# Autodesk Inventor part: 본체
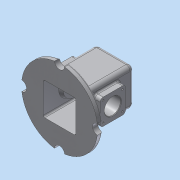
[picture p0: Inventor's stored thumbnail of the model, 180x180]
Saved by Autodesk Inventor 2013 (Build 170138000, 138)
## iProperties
Created: 2018-07
Part Number: 본체
Material: 알루미늄 6061
Document SubType Name: Modeling
Designer: Administrator
Density: 2.71 g/cm^3
Mass: 912.845 g
Surface Area: 1019.25 cm^2
Volume: 336.843 cm^3
Author: Administrator
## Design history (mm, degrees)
sketch "스케치1"
  geometry: L1 (0, 0)-(-99.447, 0); L2 (0, 0)-(0, -89.26); C1 r 75 at (0, 0); 1 further point
  constraints: 4 end point, 1 centre point, 1 coincident, 1 horizontal, 1 perpendicular
  dimensions: "d0" = 150 diameter of C1
extrude "돌출1" new body sketch "스케치1" distance "d2" = 10; taper "d3" = 0 deg
sketch "스케치2"
  geometry: L1 (0, 0)-(98.616, 0); L2 (0, 0)-(0, 93.63); C1 r 10 at (0, 75); C2 r 10 at (-75, 0); C3 r 10 at (0, -75); C4 r 10 at (75, 0)
  constraints: 4 centre point, 4 end point, 1 horizontal, 1 perpendicular, 1 point on line, 1 vertical alignment, 10 other
  dimensions: "d4" = 20 diameter of C1; "d8" = 360 deg dimension on L1.start C1.centre (derived)
extrude "돌출2" cut sketch "스케치2" distance "d10" = 10; taper "d11" = 0 deg
sketch "스케치3"
  geometry: L1 (-37, -37)-(37, -37); L2 (37, -37)-(37, 37); L3 (37, 37)-(-37, 37); L4 (-37, 37)-(-37, -37); L5 (-37, -37)-(37, 37); L6 (37, -37)-(-37, 37); A1 r 75 centre (0, 0) between (9.978, -74.333) and (74.333, -9.978) reference
  constraints: 12 end point, 2 midpoint, 2 parallel, 1 horizontal, 1 perpendicular
  dimensions: "d12" = 74 distance between parallel lines of L2 L4; "d14" = 74 distance between parallel lines of L3 L1
extrude "돌출3" join sketch "스케치3" distance "d15" = 100; taper "d16" = 0 deg
sketch "스케치4"
  geometry: L1 (-20, -20)-(20, -20); L2 (20, -20)-(20, 20); L3 (20, 20)-(-20, 20); L4 (-20, 20)-(-20, -20); L5 (-20, -20)-(20, 20); L6 (20, -20)-(-20, 20); 1 further point
  constraints: 12 end point, 2 midpoint, 2 parallel, 1 horizontal, 1 perpendicular
  dimensions: "d17" = 40 distance between parallel lines of L3 L1; "d19" = 40 distance between parallel lines of L4 L2
extrude "돌출4" join sketch "스케치4" distance "d20" = 7; taper "d21" = 0 deg
sketch "스케치5"
  geometry: C1 r 17.5 at (0, 0); 1 further point
  constraints: 1 centre point, 1 coincident
  dimensions: "d24" = 35 diameter of C1
extrude "돌출5" join sketch "스케치5" distance "d22" = 3; taper "d23" = 0 deg
sketch "스케치6"
  geometry: L1 (-32, 0)-(-32, 105); L2 (-32, 105)-(32, 105); L3 (32, 105)-(32, 0); L4 (32, 0)-(-32, 0); L5 (37, 110)-(-37, 110) reference; L6 (-37, 10)-(-37, 110) reference; L7 (37, 10)-(37, 110) reference; 1 further point
  constraints: 8 end point, 2 parallel, 1 midpoint, 1 perpendicular, 1 vertical
  dimensions: "d26" = 5 distance between parallel lines of L5 L2; "d27" = 5 distance between parallel lines of L7 L3; "d28" = 5 distance between parallel lines of L6 L1
extrude "돌출6" cut sketch "스케치6" stored distance "d29" = 64; taper "d30" = 0 deg
sketch "스케치8"
  geometry: L1 (12, 20)-(62, 20); L2 (62, 20)-(62, 70); L3 (62, 70)-(12, 70); L4 (12, 70)-(12, 20); L5 (12, 20)-(62, 70); L6 (62, 20)-(12, 70); L7 (37, -10)-(37, 143.948); L8 (46.978, -10)-(111.333, -10) reference; 2 further points
  constraints: 14 end point, 3 midpoint, 3 parallel, 1 horizontal, 1 perpendicular, 1 point on line
  dimensions: "d31" = 50 distance between parallel lines of L3 L1; "d33" = 50 distance between parallel lines of L4 L2; "d34" = 55 distance from line of point (37, 45) L8
extrude "돌출7" join sketch "스케치8" distance "d35" = 13; taper "d36" = 0 deg
sketch "스케치9"
  geometry: L1 (12, 20)-(62, 20); L2 (62, 20)-(62, 70); L3 (62, 70)-(12, 70); L4 (12, 70)-(12, 20); L5 (12, 20)-(62, 70); L6 (62, 20)-(12, 70); L7 (37, -10)-(37, 135.197); L8 (46.978, -10)-(111.333, -10) reference; 2 further points
  constraints: 14 end point, 3 midpoint, 3 parallel, 1 horizontal, 1 perpendicular, 1 point on line
  dimensions: "d37" = 50 distance between parallel lines of L3 L1; "d39" = 50 distance between parallel lines of L4 L2; "d40" = 55 distance from line of point (37, 45) L8
extrude "돌출8" join sketch "스케치9" distance "d41" = 13; taper "d42" = 0 deg
sketch "스케치10"
  geometry: L1 (-89.326, 55)-(79.755, 55); L2 (32, 0)-(-32, 0) reference; L3 (-32, 80)-(-25, 77.452); L4 (-25, 77.452)-(-25, 32.548); L5 (-25, 32.548)-(-32, 30); L6 (-32, 30)-(-32, 80); L7 (-32, 0)-(-32, 105) reference; L8 (32, 105)-(32, 0) reference; L9 (-32, 55)-(-32, 80); L10 (-25, 55)-(-25, 77.452); L11 (-25, 55)-(-32, 55); L12 (0, 0)-(0, 157.178); L13 (25, 55)-(25, 77.452); L14 (32, 55)-(32, 80); L15 (32, 80)-(25, 77.452); L16 (25, 55)-(32, 55)
  constraints: 26 end point, 4 symmetric about line, 2 collinear, 2 midpoint, 2 perpendicular, 1 horizontal, 1 point on line, 1 vertical
  dimensions: "d43" = 55 distance between parallel lines of L1 L2; "d45" = 7 distance between parallel lines of L7 L4; "d46" = 110 deg angle of L5 L7; "d47" = 110 deg angle of L7 L3; "d48" = 7 distance between parallel lines of L4 L6; "d49" = 25 distance from line of L3.start L1
revolve "회전1" sketch "스케치10" stored, may be unused: angle "d50" = 90 deg
sketch "스케치11"
  geometry: L1 (12, 70)-(12, 20) reference; L2 (12, 20)-(62, 70); L3 (62, 20)-(12, 70); C1 r 16 at (37, 45); 1 further point
  constraints: 4 end point, 1 centre point, 1 perpendicular, 1 point on line
  dimensions: "d51" = 32 diameter of C1
extrude "돌출9" cut sketch "스케치11" distance "d53" = 110; taper "d54" = 0 deg
sketch "스케치12"
  geometry: C1 r 17.5 at (0, 0) reference; C2 r 14 at (0, 0)
  constraints: 1 centre point, 1 coincident
  dimensions: "d55" = 28 diameter of C2
extrude "돌출10" cut sketch "스케치12" distance "d57" = 4; taper "d58" = 0 deg
sketch "스케치13"
  geometry: C1 r 14 at (0, 0) reference; C2 r 10.5 at (0, 0)
  constraints: 1 centre point, 1 coincident
  dimensions: "d59" = 21 diameter of C2
extrude "돌출11" cut sketch "스케치13" distance "d61" = 110; taper "d62" = 0 deg
fillet "모깎기1" dims "d63" = 6
fillet "모깎기2" dims "d64" = 6
sketch "스케치15"
  geometry: A1 r 6 centre (56, 26) between (56, 20) and (62, 26) reference; A2 r 6 centre (56, 64) between (62, 64) and (56, 70) reference; A3 r 6 centre (18, 64) between (18, 70) and (12, 64) reference; A4 r 6 centre (18, 26) between (12, 26) and (18, 20) reference; 5 further points
  constraints: 4 coincident
hole "구멍1" sketch "스케치15" at (18, 64), (18, 26), (56, 26), (56, 64) diameter "d65" = 3.459; stored, may be unused: countersink angle "d69" = 90 deg, drill point angle "d71" = 118 deg; dims "d66" = 8, "d67" = 4, "d68" = 2, "d70" = 10
fillet "모깎기3" dims "d72" = 8
fillet "모깎기4" dims "d73" = 3
fillet "모깎기5" dims "d74" = 3
fillet "모깎기6" dims "d75" = 3
fillet "모깎기7" dims "d76" = 3
fillet "모깎기8" dims "d77" = 3
fillet "모깎기9" dims "d78" = 3
sketch "스케치17"
  geometry: L1 (46.5, 18)-(11.5, 18) reference; L2 (66, -89)-(66, 0) reference; 2 further points
  constraints: 1 other
  dimensions: "d79" = 30 distance from line of L1 point (29, -12); "d80" = 37 distance from line of point (29, -12) L2
feature "엠보싱1" sketch "스케치17" dims "d81" = 0.5, "d82" = 0
chamfer "모따기1" distance "d83" = 1; stored, may be unused: second distance "d84" = 2, angle "d85" = 45 deg
node "솔리드1"
mirror "대칭1"
